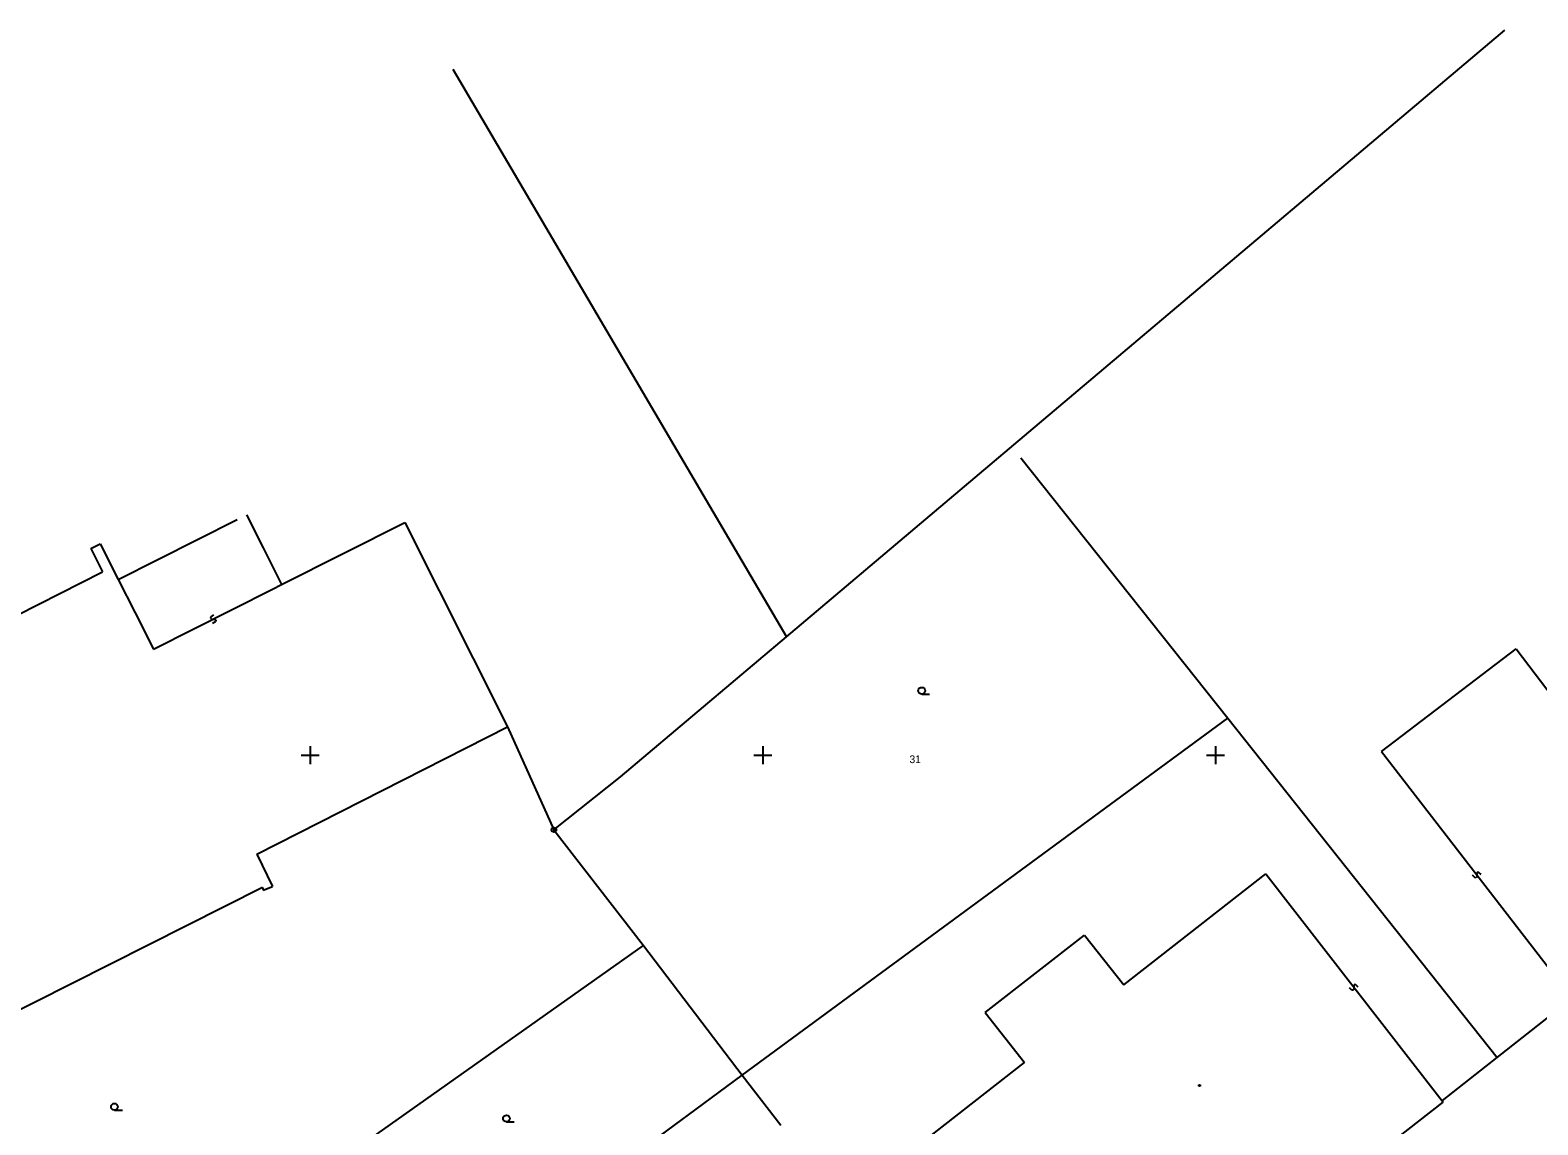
# Model space of a CAD drawing. Extents: x -492811 to -492366, y -1127107 to -1126748.
# Drawn here: x -492652.4 to -492585.8, y -1126796.3 to -1126747.9 of the extents above; entities that cross this region are included whole.
import ezdxf

# ---------------------------------------------------------------- set-up
doc = ezdxf.new("R2010")
doc.units = 0
doc.layers.add('katastrální mapa', color=7, linetype='Continuous')
doc.layers.add('síť', color=7, linetype='Continuous')

msp = doc.modelspace()

# ---------------------------------------------------------------- linework, layer by layer
at = {"layer": 'katastrální mapa'}
for p, q in [((-492618.95, -1126774.77), (-492587.21, -1126747.95)), ((-492633.69, -1126749.67), (-492618.95, -1126774.77)), ((-492608.6, -1126766.85), (-492599.45, -1126778.37)), ((-492648.48, -1126772.24), (-492643.22, -1126769.58)), ((-492642.82, -1126769.37), (-492642.08, -1126770.84)), ((-492641.26, -1126772.46), (-492635.82, -1126769.71)), ((-492635.82, -1126769.71), (-492631.28, -1126778.75)), ((-492649.69, -1126770.86), (-492649.28, -1126770.65)), ((-492649.69, -1126770.86), (-492649.17, -1126771.9)), ((-492649.28, -1126770.65), (-492648.48, -1126772.24)), ((-492642.08, -1126770.84), (-492641.26, -1126772.46)), ((-492670.28, -1126782.58), (-492649.17, -1126771.9)), ((-492648.48, -1126772.24), (-492647.74, -1126773.7)), ((-492646.92, -1126775.32), (-492641.66, -1126772.66)), ((-492641.66, -1126772.66), (-492641.26, -1126772.46)), ((-492647.74, -1126773.7), (-492646.92, -1126775.32)), ((-492644.39, -1126773.88), (-492644.41, -1126773.94)), ((-492644.41, -1126773.94), (-492644.39, -1126773.97)), ((-492644.27, -1126773.8), (-492644.39, -1126773.88)), ((-492644.39, -1126773.97), (-492644.33, -1126773.99)), ((-492644.33, -1126773.99), (-492644.25, -1126773.99)), ((-492644.19, -1126774.1), (-492644.31, -1126774.18)), ((-492644.25, -1126773.99), (-492644.19, -1126774.01)), ((-492644.19, -1126774.01), (-492644.17, -1126774.04)), ((-492644.17, -1126774.04), (-492644.19, -1126774.1)), ((-492626.29, -1126780.96), (-492618.95, -1126774.77)), ((-492592.66, -1126779.84), (-492586.72, -1126775.3)), ((-492586.72, -1126775.3), (-492584.8, -1126777.82)), ((-492612.98, -1126777.3), (-492612.63, -1126777.3)), ((-492642.36, -1126784.38), (-492631.28, -1126778.75)), ((-492631.28, -1126778.75), (-492629.23, -1126783.3)), ((-492620.91, -1126794.14), (-492599.45, -1126778.37)), ((-492599.45, -1126778.37), (-492587.55, -1126793.36)), ((-492592.66, -1126779.84), (-492584.24, -1126790.75)), ((-492629.23, -1126783.3), (-492626.29, -1126780.96)), ((-492629.23, -1126783.3), (-492625.27, -1126788.41)), ((-492642.36, -1126784.38), (-492641.66, -1126785.8)), ((-492604.05, -1126790.15), (-492597.78, -1126785.25)), ((-492597.78, -1126785.25), (-492589.99, -1126795.28)), ((-492588.54, -1126785.41), (-492588.64, -1126785.31)), ((-492588.48, -1126785.42), (-492588.54, -1126785.41)), ((-492588.45, -1126785.39), (-492588.48, -1126785.42)), ((-492588.45, -1126785.2), (-492588.46, -1126785.25)), ((-492588.46, -1126785.25), (-492588.44, -1126785.34)), ((-492588.42, -1126785.17), (-492588.45, -1126785.2)), ((-492588.44, -1126785.34), (-492588.45, -1126785.39)), ((-492588.36, -1126785.18), (-492588.42, -1126785.17)), ((-492588.26, -1126785.28), (-492588.36, -1126785.18)), ((-492662.9, -1126796.32), (-492642.1, -1126785.84)), ((-492642.1, -1126785.84), (-492642.08, -1126785.97)), ((-492642.08, -1126785.97), (-492641.66, -1126785.8)), ((-492610.17, -1126791.38), (-492605.78, -1126787.95)), ((-492605.78, -1126787.95), (-492604.05, -1126790.15)), ((-492644.69, -1126802.14), (-492625.27, -1126788.41)), ((-492625.27, -1126788.41), (-492620.91, -1126794.14)), ((-492593.97, -1126790.38), (-492594.07, -1126790.28)), ((-492593.86, -1126790.14), (-492593.89, -1126790.17)), ((-492593.89, -1126790.17), (-492593.89, -1126790.22)), ((-492593.89, -1126790.22), (-492593.88, -1126790.31)), ((-492593.88, -1126790.31), (-492593.88, -1126790.36)), ((-492593.8, -1126790.15), (-492593.86, -1126790.14)), ((-492593.7, -1126790.25), (-492593.8, -1126790.15)), ((-492593.91, -1126790.39), (-492593.97, -1126790.38)), ((-492593.88, -1126790.36), (-492593.91, -1126790.39)), ((-492587.55, -1126793.36), (-492584.24, -1126790.75)), ((-492610.17, -1126791.38), (-492608.44, -1126793.59)), ((-492613.69, -1126797.69), (-492608.44, -1126793.59)), ((-492589.99, -1126795.28), (-492587.55, -1126793.36)), ((-492639.79, -1126808.07), (-492620.91, -1126794.14)), ((-492620.91, -1126794.14), (-492619.21, -1126796.36)), ((-492600.73, -1126794.57), (-492600.67, -1126794.57)), ((-492600.73, -1126794.63), (-492600.73, -1126794.57)), ((-492600.67, -1126794.63), (-492600.73, -1126794.63)), ((-492600.67, -1126794.57), (-492600.67, -1126794.63)), ((-492596.66, -1126800.56), (-492589.94, -1126795.34)), ((-492589.99, -1126795.28), (-492589.94, -1126795.34)), ((-492648.65, -1126795.69), (-492648.3, -1126795.69)), ((-492631.33, -1126796.21), (-492630.98, -1126796.21))]:
    msp.add_line(p, q, dxfattribs=at)
for centre, radius in [((-492612.98, -1126777.15), 0.15), ((-492629.23, -1126783.3), 0.1), ((-492629.23, -1126783.3), 0.002), ((-492648.65, -1126795.54), 0.15), ((-492631.33, -1126796.06), 0.15)]:
    msp.add_circle(centre, radius, dxfattribs=at)
at = {"layer": 'síť'}
for p, q in [((-492640, -1126779.6), (-492640, -1126780.4)), ((-492620, -1126779.6), (-492620, -1126780.4)), ((-492600, -1126779.6), (-492600, -1126780.4)), ((-492640.4, -1126780), (-492639.6, -1126780)), ((-492620.4, -1126780), (-492619.6, -1126780)), ((-492600.4, -1126780), (-492599.6, -1126780))]:
    msp.add_line(p, q, dxfattribs=at)

# ---------------------------------------------------------------- texts
at = {"layer": 'katastrální mapa'}
msp.add_text('31', height=0.34, dxfattribs=at).set_placement((-492613.52, -1126780.35))

doc.saveas('drawing.dxf')
